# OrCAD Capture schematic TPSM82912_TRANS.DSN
size D
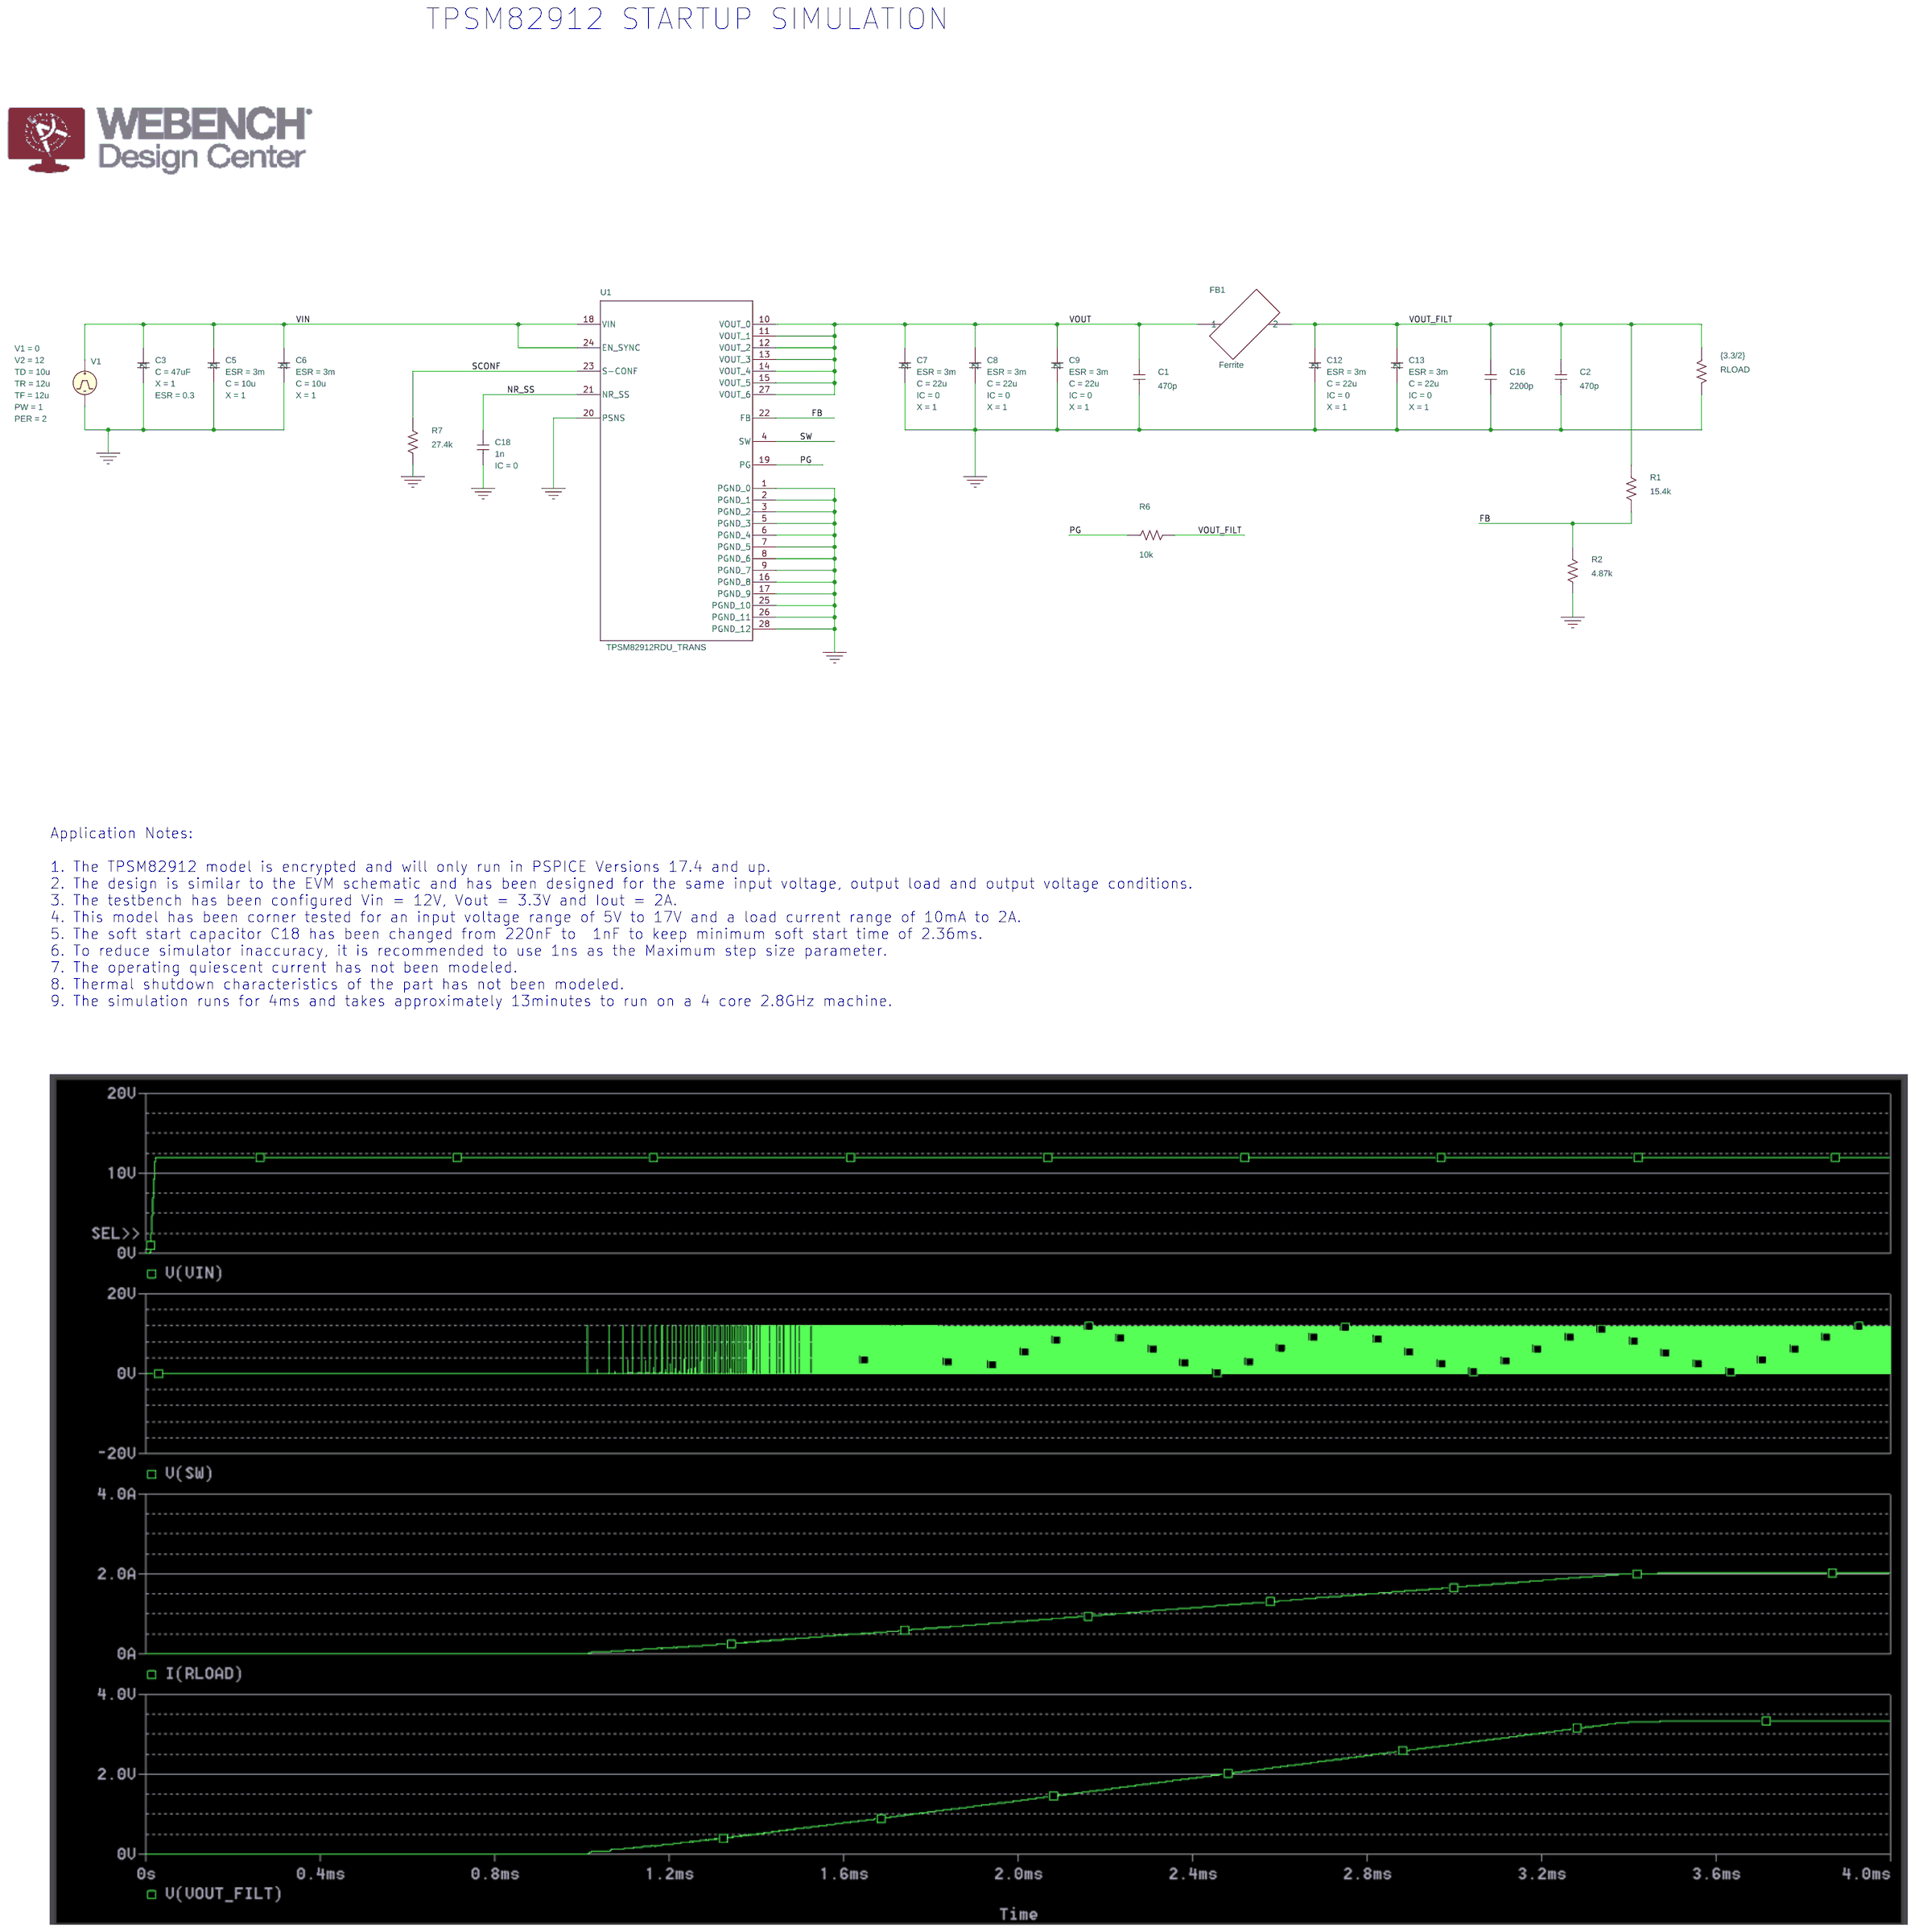
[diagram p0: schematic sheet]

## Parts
C1  470p  [RAD/CK05]
C2  470p  [RAD/CK05]
C3  CESR
C5  CESR
C6  CESR
C7  CESR
C8  CESR
C9  CESR
C12  CESR
C13  CESR
C16  2200p  [RAD/CK05]
C18  1n  [RAD/CK05]
FB1  Ferrite
R1  15.4k  [AX/RC05]
R2  4.87k  [AX/RC05]
R6  10k  [AX/RC05]
R7  27.4k  [AX/RC05]
RLOAD  {3.3/2}  [AX/RC05]
U1  TPSM82912RDU_TRANS
V1  VPULSE

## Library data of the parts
C1 C2 C16 = C
C3 = CESR_1_2: C: 47uF; ESR: 0.3; PSpiceTemplate: X^@REFDES %1 %2 @MODEL PARAMS: ?C|C=@C||C=10U| ?ESR|ESR=@ESR||ESR=2M| ?IC|IC=@IC||IC=0| ?X|X=@X||X=0|; X: 1
C5 = CESR_1: C: 10u; ESR: 3m; PSpiceTemplate: X^@REFDES %1 %2 @MODEL PARAMS: ?C|C=@C||C=10U| ?ESR|ESR=@ESR||ESR=2M| ?IC|IC=@IC||IC=0| ?X|X=@X||X=0|; X: 1
C6 = CESR_1_3: C: 10u; ESR: 3m; PSpiceTemplate: X^@REFDES %1 %2 @MODEL PARAMS: ?C|C=@C||C=10U| ?ESR|ESR=@ESR||ESR=2M| ?IC|IC=@IC||IC=0| ?X|X=@X||X=0|; X: 1
C7 = CESR_1_1: C: 22u; ESR: 3m; IC: 0; PSpiceTemplate: X^@REFDES %1 %2 @MODEL PARAMS: ?C|C=@C||C=10U| ?ESR|ESR=@ESR||ESR=2M| ?IC|IC=@IC||IC=0| ?X|X=@X||X=0|; X: 1
C8 = CESR_1_7: C: 22u; ESR: 3m; IC: 0; PSpiceTemplate: X^@REFDES %1 %2 @MODEL PARAMS: ?C|C=@C||C=10U| ?ESR|ESR=@ESR||ESR=2M| ?IC|IC=@IC||IC=0| ?X|X=@X||X=0|; X: 1
C9 = CESR_1_6: C: 22u; ESR: 3m; IC: 0; PSpiceTemplate: X^@REFDES %1 %2 @MODEL PARAMS: ?C|C=@C||C=10U| ?ESR|ESR=@ESR||ESR=2M| ?IC|IC=@IC||IC=0| ?X|X=@X||X=0|; X: 1
C12 = CESR_1_5: C: 22u; ESR: 3m; IC: 0; PSpiceTemplate: X^@REFDES %1 %2 @MODEL PARAMS: ?C|C=@C||C=10U| ?ESR|ESR=@ESR||ESR=2M| ?IC|IC=@IC||IC=0| ?X|X=@X||X=0|; X: 1
C13 = CESR_1_4: C: 22u; ESR: 3m; IC: 0; PSpiceTemplate: X^@REFDES %1 %2 @MODEL PARAMS: ?C|C=@C||C=10U| ?ESR|ESR=@ESR||ESR=2M| ?IC|IC=@IC||IC=0| ?X|X=@X||X=0|; X: 1
C18 = C: IC: 0
FB1 = Ferrite
R1 R2 R6 R7 RLOAD = R
U1 = TPSM82912RDU_TRANS
V1 = VPULSE: AC: 0; AppProp: Pulse$Voltage$1$-1; DC: 0; PER: 2; PW: 1; TD: 10u; TF: 12u; TR: 12u; V1: 0; V2: 12

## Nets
VIN: C3.1 C5.1 C6.1 U1.18(VIN) U1.24(EN_SYNC) V1.1(+)
0: C1.1 C2.1 C3.2 C5.2 C6.2 C7.2 C8.2 C9.2 C12.2 C13.2 C16.1 C18.2 R2.2 R7.2 RLOAD.2 U1.1(PGND_0) U1.2(PGND_1) U1.3(PGND_2) U1.5(PGND_3) U1.6(PGND_4) U1.7(PGND_5) U1.8(PGND_6) U1.9(PGND_7) U1.16(PGND_8) U1.17(PGND_9) U1.20(PSNS) U1.25(PGND_10) U1.26(PGND_11) U1.28(PGND_12) V1.2(-)
FB: R1.2 R2.1 U1.22(FB)
NR_SS: C18.1 U1.21(NR_SS)
PG: R6.1 U1.19(PG)
SCONF: R7.1 U1.23(S-CONF)
SW: U1.4(SW)
VOUT: C1.2 C7.1 C8.1 C9.1 FB1.1 U1.10(VOUT_0) U1.11(VOUT_1) U1.12(VOUT_2) U1.13(VOUT_3) U1.14(VOUT_4) U1.15(VOUT_5) U1.27(VOUT_6)
VOUT_FILT: C2.2 C12.1 C13.1 C16.2 FB1.2 R1.1 R6.2 RLOAD.1

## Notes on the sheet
- TPSM82912 STARTUP SIMULATION
- Application Notes:
  1. The TPSM82912 model is encrypted and will only run in PSPICE Versions 17.4 and up.
  2. The design is similar to the EVM schematic and has been designed for the same input voltage, output load and output voltage conditions.
  3. The testbench has been configured Vin = 12V, Vout = 3.3V and Iout = 2A.
  4. This model has been corner tested for an input voltage range of 5V to 17V and a load current range of 10mA to 2A.
  5. The soft start capacitor C18 has been changed from 220nF to  1nF to keep minimum soft start time of 2.36ms.
  6. To reduce simulator inaccuracy, it is recommended to use 1ns as the Maximum step size parameter.
  7. The operating quiescent current has not been modeled.
  8. Thermal shutdown characteristics of the part has not been modeled.
  9. The simulation runs for 4ms and takes approximately 13minutes to run on a 4 core 2.8GHz machine.
